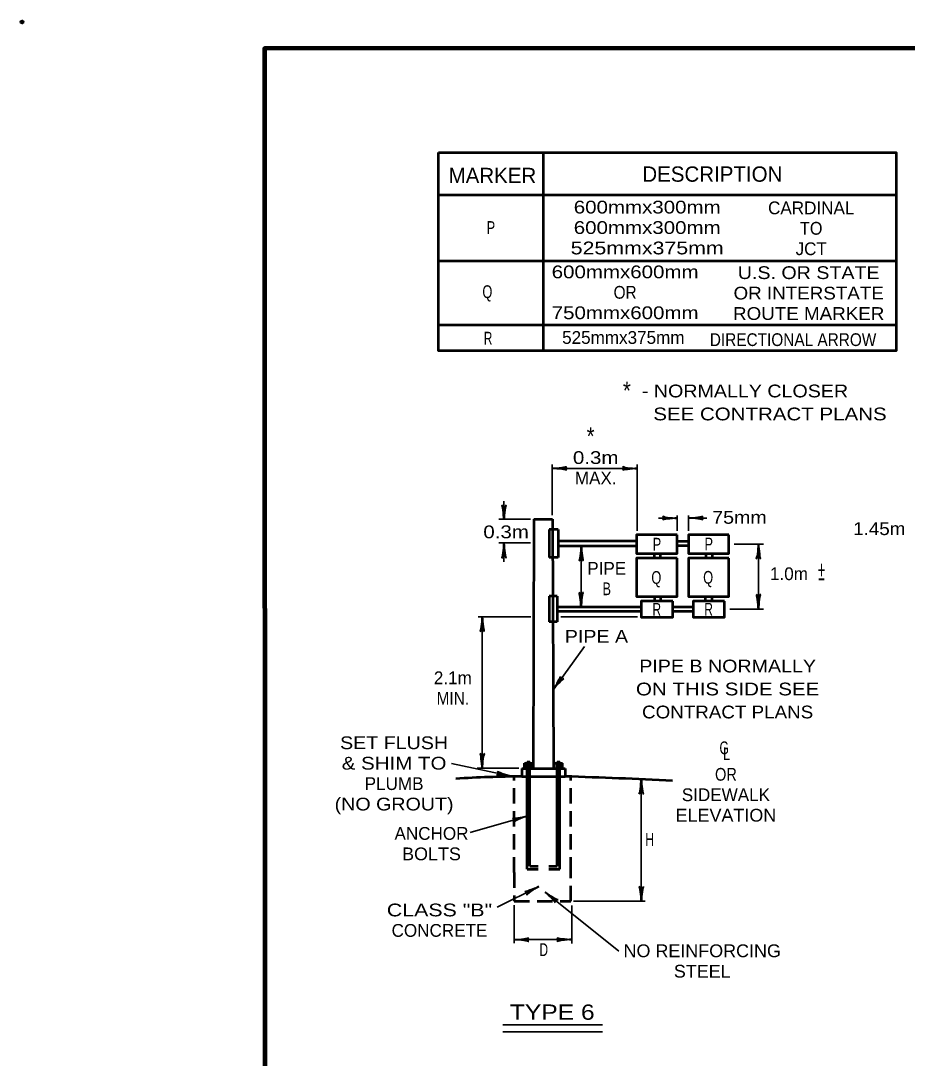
# Model space of a CAD drawing. Extents: x -274 to 582, y -298 to 246.
# Drawn here: x -273.7 to -65.4, y 2.6 to 246.4 of the extents above; entities that cross this region are included whole.
import ezdxf
from ezdxf.enums import TextEntityAlignment as Align

# ---------------------------------------------------------------- set-up
doc = ezdxf.new("R2010")
doc.units = 0
doc.header["$LTSCALE"] = 1.2
doc.header["$PDMODE"] = 32
doc.header["$PDSIZE"] = 0.6
doc.linetypes.add('MEDIUM_DASHED', pattern=[4.5, 3, -1.5])
doc.layers.add('1', color=7, linetype='Continuous', lineweight=53)

msp = doc.modelspace()

# ---------------------------------------------------------------- linework, layer by layer
at = {"layer": '1'}
for p, q in [((-150.91, 168.836), (-150.91, 215.402)), ((-175.528, 205.45), (-68, 205.45)), ((-175.528, 189.998), (-68, 189.998)), ((-175.528, 174.932), (-68, 174.932)), ((-153.128, 129.237), (-153.291, 70.694)), ((-153.128, 129.237), (-148.744, 129.237)), ((-148.744, 129.237), (-148.502, 70.694)), ((-147.453, 126.881), (-149.548, 126.881)), ((-149.548, 126.881), (-149.548, 120.279)), ((-147.453, 126.881), (-147.453, 120.279)), ((-129.037, 124.072), (-147.453, 124.072)), ((-129.037, 122.957), (-147.453, 122.957)), ((-116.845, 124.03), (-119.502, 124.03)), ((-116.845, 123.002), (-119.502, 123.002)), ((-147.453, 120.279), (-149.548, 120.279)), ((-124.818, 120.093), (-124.818, 121.213)), ((-123.396, 120.093), (-123.396, 121.213)), ((-112.626, 120.093), (-112.626, 121.213)), ((-111.204, 120.093), (-111.204, 121.213)), ((-147.643, 111.172), (-149.548, 111.172)), ((-149.548, 111.172), (-149.548, 105.17)), ((-147.643, 111.172), (-147.643, 105.17)), ((-124.818, 111.117), (-124.818, 109.993)), ((-123.396, 111.117), (-123.396, 109.993)), ((-112.786, 109.993), (-112.786, 111.117)), ((-111.236, 109.993), (-111.236, 111.117)), ((-127.914, 108.619), (-147.643, 108.619)), ((-127.914, 107.605), (-147.643, 107.605)), ((-115.722, 108.619), (-120.511, 108.619)), ((-115.722, 107.605), (-120.51, 107.605)), ((-147.643, 105.17), (-149.548, 105.17)), ((-156.006, 70.694), (-145.787, 70.694)), ((-156.006, 70.694), (-156.006, 68.833)), ((-155.367, 70.694), (-155.367, 71.972)), ((-155.367, 71.972), (-153.45, 71.972)), ((-154.824, 71.972), (-154.824, 72.068)), ((-154.824, 72.068), (-153.993, 72.068)), ((-154.728, 72.291), (-154.089, 72.291)), ((-154.728, 72.068), (-154.728, 72.291)), ((-154.728, 47.061), (-154.728, 71.972)), ((-154.089, 72.068), (-154.089, 72.291)), ((-154.089, 47.788), (-154.089, 71.972)), ((-153.993, 71.972), (-153.993, 72.068)), ((-153.45, 70.694), (-153.45, 71.972)), ((-148.342, 71.972), (-146.425, 71.972)), ((-148.342, 70.694), (-148.342, 71.972)), ((-147.799, 71.972), (-147.799, 72.068)), ((-147.799, 72.068), (-146.968, 72.068)), ((-147.703, 72.291), (-147.064, 72.291)), ((-147.703, 72.068), (-147.703, 72.291)), ((-147.703, 47.788), (-147.703, 71.972)), ((-147.064, 72.068), (-147.064, 72.291)), ((-147.064, 47.061), (-147.064, 71.972)), ((-146.968, 71.972), (-146.968, 72.068)), ((-146.425, 70.694), (-146.425, 71.972)), ((-145.787, 70.694), (-145.787, 68.833)), ((-156.006, 68.833), (-145.787, 68.833)), ((-154.728, 47.061), (-152.173, 47.061)), ((-154.089, 47.788), (-152.173, 47.788)), ((-149.617, 47.788), (-147.703, 47.788)), ((-149.617, 47.061), (-147.064, 47.061))]:
    msp.add_line(p, q, dxfattribs=at)
at = {"layer": '1', "lineweight": 35}
for p, q in [((-148.848, 130.195), (-148.848, 142.145)), ((-128.904, 126.548), (-128.904, 142.145)), ((-128.904, 141.186), (-148.848, 141.186)), ((-160.171, 133.468), (-160.171, 129.112)), ((-153.93, 129.237), (-161.407, 129.237)), ((-119.502, 129.522), (-123.858, 129.522)), ((-119.502, 126.548), (-119.502, 130.158)), ((-116.845, 126.548), (-116.845, 130.158)), ((-112.489, 129.522), (-116.845, 129.522)), ((-153.93, 123.714), (-161.407, 123.714)), ((-160.171, 123.595), (-160.171, 119.239)), ((-142.032, 122.957), (-142.032, 108.619)), ((-106.11, 123.402), (-99.175, 123.402)), ((-100.376, 123.402), (-100.376, 108.142)), ((-107.119, 108.142), (-99.175, 108.142)), ((-153.824, 106.315), (-166.217, 106.315)), ((-165.283, 106.315), (-165.283, 70.745)), ((-128.793, 106.315), (-146.772, 106.315)), ((-148.551, 89.266), (-141.263, 99.334)), ((-158.452, 68.898), (-172.517, 71.882)), ((-156.654, 70.745), (-166.446, 70.745)), ((-127.902, 39.504), (-127.902, 68.162)), ((-154.728, 59.516), (-168.135, 55.7)), ((-151.972, 42.969), (-161.749, 38.127)), ((-150.484, 41.665), (-133.166, 27.789)), ((-143.869, 39.504), (-127.031, 39.504)), ((-157.754, 38.578), (-157.754, 29.641)), ((-144.264, 38.551), (-144.264, 29.614)), ((-157.754, 30.512), (-144.264, 30.512)), ((-160.475, 10.472), (-137.002, 10.472)), ((-160.475, 8.833), (-137.002, 8.833))]:
    msp.add_line(p, q, dxfattribs=at)
at = {"layer": '1', "linetype": 'MEDIUM_DASHED'}
for p, q in [((-157.768, 46.249), (-157.768, 68.815)), ((-144.431, 46.249), (-144.431, 68.791))]:
    msp.add_line(p, q, dxfattribs=at)
at = {"layer": '1', "lineweight": 158}
msp.add_lwpolyline([(575.293, 239.961), (-216.407, 239.861), (-216.307, -286.139)], dxfattribs=at)
at = {"layer": '1'}
for points in [[(-175.528, 215.402), (-68, 215.402), (-68, 168.836), (-175.528, 168.836)], [(-119.502, 125.59), (-129.037, 125.59), (-129.037, 121.213), (-119.502, 121.213)], [(-107.31, 125.59), (-116.845, 125.59), (-116.845, 121.213), (-107.31, 121.213)], [(-119.502, 120.093), (-129.037, 120.093), (-129.037, 111.117), (-119.502, 111.117)], [(-107.31, 120.093), (-116.845, 120.093), (-116.845, 111.117), (-107.31, 111.117)], [(-120.511, 109.993), (-127.914, 109.993), (-127.914, 106.29), (-120.511, 106.29)], [(-108.319, 109.993), (-115.722, 109.993), (-115.722, 106.29), (-108.319, 106.29)]]:
    msp.add_lwpolyline(points, close=True, dxfattribs=at)
at = {"layer": '1', "linetype": 'MEDIUM_DASHED'}
msp.add_lwpolyline([(-157.768, 46.249), (-157.768, 39.538), (-144.431, 39.538), (-144.431, 46.249)], dxfattribs=at)
msp.add_lwpolyline([(-157.768, 46.249), (-157.768, 39.538), (-144.431, 39.538), (-144.431, 46.249)], dxfattribs=at)
at = {"layer": '1'}
for centre, radius, start, end in [((-153.545, -227.577), 296.421, 90.47573, 93.46734), ((-184.847, -1209.777), 1279.207, 87.12083, 88.25023)]:
    msp.add_arc(centre, radius, start, end, dxfattribs=at)
at = {"layer": '1', "lineweight": 40}
for centre, major_axis, ratio, start_param, end_param in [((-147.503, 141.44), (-2.108, -0.211), 0.07063, 0.8650754, 3.1424706), ((-130.213, 141.518), (2.143, -0.187), 0.122415, 3.1415927, 5.386832), ((-130.213, 141.518), (2.143, -0.187), 0.122415, 3.1415927, 5.386832), ((-147.538, 140.855), (-2.143, 0.187), 0.122415, 3.1415927, 5.386832), ((-130.249, 140.932), (2.108, 0.211), 0.07063, 0.8650754, 3.1424706), ((-130.249, 140.932), (2.108, 0.211), 0.07063, 0.8650754, 3.1424706), ((-160.425, 130.457), (0.211, -2.108), 0.07063, 0.8650754, 3.1424706), ((-159.84, 130.422), (-0.187, -2.143), 0.122415, 3.1415927, 5.386832), ((-120.811, 129.853), (2.143, -0.187), 0.122415, 3.1415927, 5.386832), ((-120.847, 129.268), (2.108, 0.211), 0.07063, 0.8650754, 3.1424706), ((-115.501, 129.776), (-2.108, -0.211), 0.07063, 0.8650754, 3.1424706), ((-115.536, 129.19), (-2.143, 0.187), 0.122415, 3.1415927, 5.386832), ((-160.503, 122.285), (0.187, 2.143), 0.122415, 3.1415927, 5.386832), ((-159.917, 122.25), (-0.211, 2.108), 0.07063, 0.8650754, 3.1424706), ((-142.354, 121.637), (0.187, 2.143), 0.122415, 3.1415927, 5.386832), ((-141.769, 121.602), (-0.211, 2.108), 0.07063, 0.8650754, 3.1424706), ((-100.707, 122.092), (0.187, 2.143), 0.122415, 3.1415927, 5.386832), ((-100.122, 122.057), (-0.211, 2.108), 0.07063, 0.8650754, 3.1424706), ((-142.296, 109.974), (0.211, -2.108), 0.07063, 0.8650754, 3.1424706), ((-141.71, 109.939), (-0.187, -2.143), 0.122415, 3.1415927, 5.386832), ((-100.629, 109.486), (0.211, -2.108), 0.07063, 0.8650754, 3.1424706), ((-100.044, 109.451), (-0.187, -2.143), 0.122415, 3.1415927, 5.386832), ((-165.614, 105.006), (0.187, 2.143), 0.122415, 3.1415927, 5.386832), ((-165.029, 104.97), (-0.211, 2.108), 0.07063, 0.8650754, 3.1424706), ((-147.968, 90.504), (-1.065, -1.831), 0.07063, 0.8650754, 3.1424706), ((-147.515, 90.132), (-1.408, -1.626), 0.122415, 3.1415927, 5.386832), ((-165.537, 72.09), (0.211, -2.108), 0.07063, 0.8650754, 3.1424706), ((-165.537, 72.09), (0.211, -2.108), 0.07063, 0.8650754, 3.1424706), ((-164.951, 72.055), (-0.187, -2.143), 0.122415, 3.1415927, 5.386832), ((-164.951, 72.055), (-0.187, -2.143), 0.122415, 3.1415927, 5.386832), ((-159.801, 68.845), (2.135, -0.261), 0.122415, 0.8963533, 3.1415927), ((-159.714, 69.425), (2.018, -0.644), 0.07063, 3.1407148, 5.41811), ((-128.156, 66.817), (0.211, 2.108), 0.07063, 3.1407148, 5.41811), ((-127.571, 66.852), (-0.187, 2.143), 0.122415, 0.8963533, 3.1415927), ((-156.091, 59.392), (2.085, 0.374), 0.07063, 3.1407148, 5.41811), ((-155.897, 58.839), (2.01, 0.767), 0.122415, 0.8963533, 3.1415927), ((-153.29, 42.6), (1.982, 0.747), 0.07063, 3.1407148, 5.41811), ((-153.29, 42.6), (1.982, 0.747), 0.07063, 3.1407148, 5.41811), ((-152.998, 42.091), (1.837, 1.119), 0.122415, 0.8963533, 3.1415927), ((-152.998, 42.091), (1.837, 1.119), 0.122415, 0.8963533, 3.1415927), ((-149.593, 40.626), (-1.513, 1.482), 0.07063, 3.1407148, 5.41811), ((-149.255, 41.105), (-1.789, 1.194), 0.122415, 0.8963533, 3.1415927), ((-128.234, 40.813), (0.187, -2.143), 0.122415, 0.8963533, 3.1415927), ((-127.648, 40.848), (-0.211, -2.108), 0.07063, 3.1407148, 5.41811), ((-156.409, 30.258), (-2.108, 0.211), 0.07063, 3.1407148, 5.41811), ((-156.409, 30.258), (-2.108, 0.211), 0.07063, 3.1407148, 5.41811), ((-156.444, 30.843), (-2.143, -0.187), 0.122415, 0.8963533, 3.1415927), ((-156.444, 30.843), (-2.143, -0.187), 0.122415, 0.8963533, 3.1415927), ((-145.574, 30.18), (2.143, 0.187), 0.122415, 0.8963533, 3.1415927), ((-145.574, 30.18), (2.143, 0.187), 0.122415, 0.8963533, 3.1415927), ((-145.609, 30.766), (2.108, -0.211), 0.07063, 3.1407148, 5.41811), ((-145.609, 30.766), (2.108, -0.211), 0.07063, 3.1407148, 5.41811)]:
    msp.add_ellipse(centre, major_axis=major_axis, ratio=ratio, start_param=start_param, end_param=end_param, dxfattribs=at)
at = {"layer": '1'}
msp.add_point((-273.407, 246.061), dxfattribs=at)

# ---------------------------------------------------------------- texts
for s, p in [('DESCRIPTION', (-127.661, 208.542)), ('MARKER', (-173.177, 208.211))]:
    msp.add_text(s, height=3.6, dxfattribs=at).set_placement(p)
for s, height, width, p in [('600mmx300mm', 3, 1.2, (-126.52, 201.08)), ('P', 3, 0.75, (-163.246, 196.28)), ('600mmx300mm', 3, 1.2, (-126.52, 196.28)), ('TO', 3, 0.95, (-87.982, 196.102)), ('525mmx375mm', 3, 1.25, (-126.52, 191.48)), ('600mmx600mm', 3, 1.2, (-131.705, 185.86)), ('U.S. OR STATE', 3, 1.15, (-88.575, 185.682)), ('Q', 3, 0.75, (-164.073, 181.214)), ('OR', 3, 0.9, (-131.705, 181.06)), ('OR INTERSTATE', 3, 1.1, (-88.575, 180.882)), ('750mmx600mm', 3, 1.2, (-131.705, 176.26)), ('ROUTE MARKER', 3, 1.1, (-88.575, 176.082)), ('R', 3, 0.7, (-163.908, 170.286)), ('DIRECTIONAL ARROW', 3, 0.9, (-92.244, 169.943)), ('*', 4.2, 0.85, (-131.292, 157.375)), ('*', 4.2, 0.85, (-139.82, 146.674)), ('0.3m', 3, 1.2, (-138.619, 142.241)), ('75mm', 3, 1.15, (-104.832, 128.201)), ('0.3m', 3, 1.2, (-159.671, 124.79)), ('1.45m', 3, 1.1, (-71.995, 125.534)), ('P', 3, 0.75, (-124.231, 121.891)), ('P', 3, 0.75, (-112.056, 121.926)), ('Q', 3, 0.75, (-124.371, 114.074)), ('Q', 3, 0.75, (-112.195, 114.109)), ('+', 4.2, 0.55, (-85.573, 115.274)), ('B', 3, 0.75, (-136.026, 111.419)), ('R', 3, 0.7, (-124.266, 106.571)), ('R', 3, 0.7, (-112.091, 106.605)), ('PIPE A', 3, 1.15, (-138.447, 100.241)), ('PIPE B NORMALLY', 3, 1.15, (-107.621, 93.272)), ('ON THIS SIDE SEE', 3, 1.2, (-107.621, 87.871)), ('MIN.', 3, 0.9, (-172.187, 85.71)), ('CONTRACT PLANS', 3, 1.1, (-107.621, 82.472)), ('SET FLUSH', 3, 1.15, (-185.988, 75.245)), ('G', 3, 0.7, (-108.435, 74.058)), ('L', 3, 0.75, (-107.851, 72.695)), ('& SHIM TO', 3, 1.2, (-185.988, 70.445)), ('OR', 3, 0.85, (-108.022, 67.831)), ('(NO GROUT)', 3, 1.15, (-185.988, 60.845)), ('ELEVATION', 3, 1.05, (-108.022, 58.231)), ('H', 3, 0.7, (-125.936, 52.533)), ('BOLTS', 3, 1.05, (-177.198, 49.145)), ('CLASS "B"', 3, 1.25, (-175.321, 35.963)), ('D', 3, 0.7, (-150.826, 26.647)), ('NO REINFORCING', 3, 1.05, (-113.59, 26.379)), ('STEEL', 3, 1.05, (-113.59, 21.579))]:
    msp.add_text(s, height=height, dxfattribs=dict(at, width=width)).set_placement(p, align=Align.CENTER)
for s, height, p in [('CARDINAL', 3, (-87.982, 200.902)), ('JCT', 3, (-87.982, 191.302)), ('525mmx375mm', 3, (-132.129, 170.452)), ('MAX.', 3, (-138.619, 137.441)), ('PIPE', 3, (-136.026, 116.219)), ('1.0m', 3, (-93.208, 114.95)), ('-', 4.2, (-85.573, 113.51)), ('2.1m', 3, (-172.187, 90.51)), ('PLUMB', 3, (-185.988, 65.645)), ('SIDEWALK', 3, (-108.022, 63.031)), ('ANCHOR', 3, (-177.197, 53.945)), ('CONCRETE', 3, (-175.321, 31.163))]:
    msp.add_text(s, height=height, dxfattribs=at).set_placement(p, align=Align.CENTER)
for s, height, width, p in [('- NORMALLY CLOSER', 3, 1.15, (-127.765, 157.887)), ('  SEE CONTRACT PLANS', 3, 1.2, (-127.765, 152.487)), ('TYPE 6', 3.6, 1.2, (-158.778, 11.667))]:
    msp.add_text(s, height=height, dxfattribs=dict(at, width=width)).set_placement(p)

doc.saveas('drawing.dxf')
